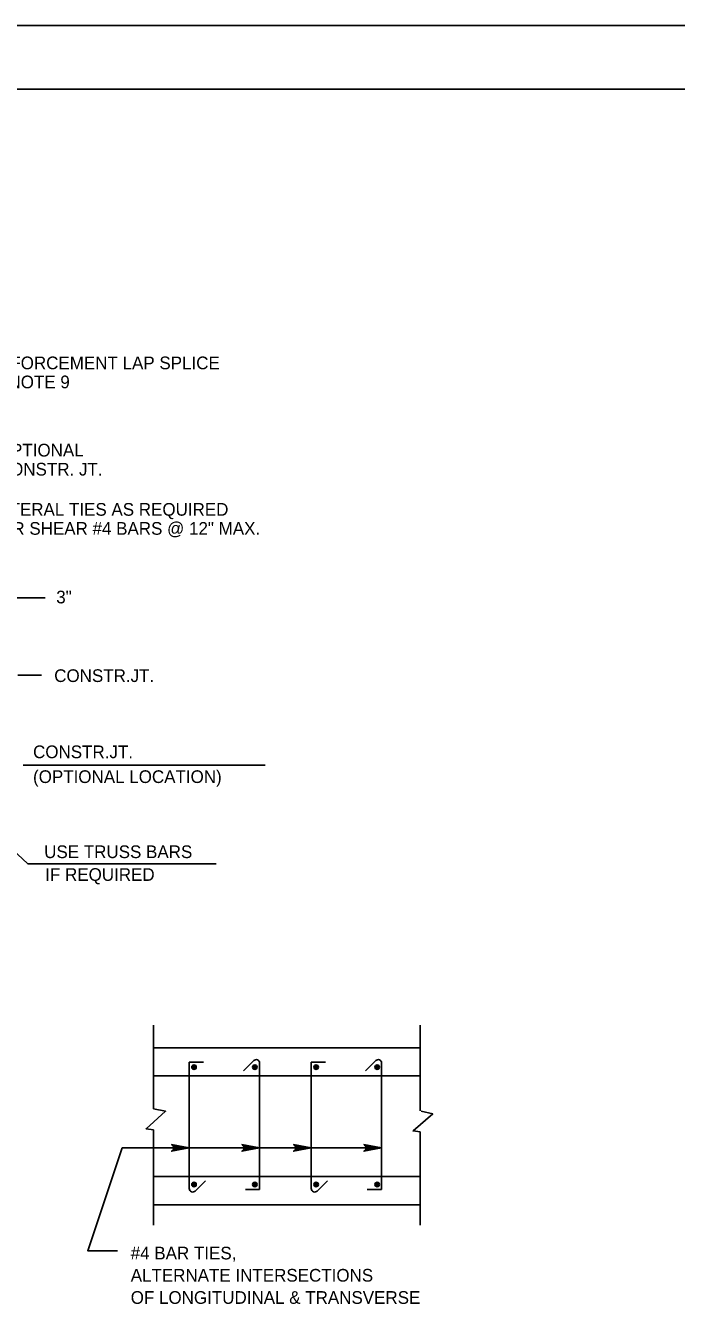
# Model space of a CAD drawing. Extents: x 639028 to 639883, y 298843 to 300031.
# Drawn here: x 639429.9 to 639583.6, y 299727.9 to 300031.1 of the extents above; entities that cross this region are included whole.
import ezdxf

# ---------------------------------------------------------------- set-up
doc = ezdxf.new("R2010")
doc.units = 0
for name, color, linetype in [('2', 7, 'Continuous'), ('52', 7, 'Continuous'), ('54', 7, 'Continuous'), ('PLT-BNDY', 7, 'Continuous')]:
    doc.layers.add(name, color=color, linetype=linetype)

msp = doc.modelspace()

# ---------------------------------------------------------------- linework, layer by layer
at = {"layer": '2'}
for p, q in [((639067.74, 300016.08), (639853.74, 300016.08)), ((639423.86, 299895.83), (639434.45, 299895.83)), ((639427.99, 299877.58), (639433.61, 299877.58)), ((639429.24, 299856.33), (639486.49, 299856.33)), ((639408.49, 299853.45), (639430.36, 299832.95)), ((639430.36, 299832.95), (639474.86, 299832.95)), ((639460.06, 299794.86), (639460.06, 299775.11)), ((639523.06, 299794.86), (639523.06, 299774.61)), ((639460.06, 299789.49), (639523.06, 299789.49)), ((639460.06, 299782.86), (639523.06, 299782.86)), ((639460.06, 299770.11), (639460.06, 299747.61)), ((639523.06, 299769.61), (639523.06, 299747.61)), ((639460.06, 299759.11), (639523.06, 299759.11)), ((639460.06, 299752.36), (639523.06, 299752.36))]:
    msp.add_line(p, q, dxfattribs=at)
for points in [[(639460.06, 299775.11), (639462.93, 299774.49), (639458.31, 299770.36), (639460.06, 299770.11)], [(639523.31, 299774.49), (639526.06, 299773.86), (639521.43, 299769.86), (639523.06, 299769.61)]]:
    msp.add_lwpolyline(points, dxfattribs=at)
at = {"layer": '52'}
msp.add_line((639452.63, 299765.83), (639513.98, 299765.83), dxfattribs=at)
for points in [[(639452.63, 299765.83), (639444.52, 299741.53), (639451.59, 299741.53)], [(639468.52, 299765.83), (639464.33, 299765.04), (639464.49, 299765.15), (639464.65, 299765.26), (639464.74, 299765.41), (639464.82, 299765.55), (639464.84, 299765.69), (639464.87, 299765.83), (639464.84, 299765.97), (639464.82, 299766.11), (639464.74, 299766.25), (639464.65, 299766.39), (639464.49, 299766.5), (639464.33, 299766.61), (639468.52, 299765.83), (639464.49, 299766.5), (639464.65, 299766.39), (639468.52, 299765.83), (639464.74, 299766.25), (639464.82, 299766.11), (639468.52, 299765.83), (639464.84, 299765.97), (639464.87, 299765.83), (639468.52, 299765.83), (639464.84, 299765.69), (639464.82, 299765.55), (639468.52, 299765.83), (639464.74, 299765.41), (639464.65, 299765.26), (639468.52, 299765.83), (639464.49, 299765.15)], [(639485.15, 299765.83), (639480.96, 299765.04), (639481.12, 299765.15), (639481.28, 299765.26), (639481.36, 299765.41), (639481.45, 299765.55), (639481.47, 299765.69), (639481.5, 299765.83), (639481.47, 299765.97), (639481.45, 299766.11), (639481.36, 299766.25), (639481.28, 299766.39), (639481.12, 299766.5), (639480.96, 299766.61), (639485.15, 299765.83), (639481.12, 299766.5), (639481.28, 299766.39), (639485.15, 299765.83), (639481.36, 299766.25), (639481.45, 299766.11), (639485.15, 299765.83), (639481.47, 299765.97), (639481.5, 299765.83), (639485.15, 299765.83), (639481.47, 299765.69), (639481.45, 299765.55), (639485.15, 299765.83), (639481.36, 299765.41), (639481.28, 299765.26), (639485.15, 299765.83), (639481.12, 299765.15)], [(639497.35, 299765.83), (639493.16, 299765.04), (639493.32, 299765.15), (639493.48, 299765.26), (639493.56, 299765.41), (639493.65, 299765.55), (639493.67, 299765.69), (639493.7, 299765.83), (639493.67, 299765.97), (639493.65, 299766.11), (639493.56, 299766.25), (639493.48, 299766.39), (639493.32, 299766.5), (639493.16, 299766.61), (639497.35, 299765.83), (639493.32, 299766.5), (639493.48, 299766.39), (639497.35, 299765.83), (639493.56, 299766.25), (639493.65, 299766.11), (639497.35, 299765.83), (639493.67, 299765.97), (639493.7, 299765.83), (639497.35, 299765.83), (639493.67, 299765.69), (639493.65, 299765.55), (639497.35, 299765.83), (639493.56, 299765.41), (639493.48, 299765.26), (639497.35, 299765.83), (639493.32, 299765.15)], [(639513.98, 299765.83), (639509.78, 299765.04), (639509.95, 299765.15), (639510.11, 299765.26), (639510.19, 299765.41), (639510.27, 299765.55), (639510.3, 299765.69), (639510.32, 299765.83), (639510.3, 299765.97), (639510.27, 299766.11), (639510.19, 299766.25), (639510.11, 299766.39), (639509.95, 299766.5), (639509.78, 299766.61), (639513.98, 299765.83), (639509.95, 299766.5), (639510.11, 299766.39), (639513.98, 299765.83), (639510.19, 299766.25), (639510.27, 299766.11), (639513.98, 299765.83), (639510.3, 299765.97), (639510.32, 299765.83), (639513.98, 299765.83), (639510.3, 299765.69), (639510.27, 299765.55), (639513.98, 299765.83), (639510.19, 299765.41), (639510.11, 299765.26), (639513.98, 299765.83), (639509.95, 299765.15)]]:
    msp.add_lwpolyline(points, dxfattribs=at)
at = {"layer": '54'}
for p, q in [((639483.75, 299786.46), (639481.33, 299784.05)), ((639512.58, 299786.46), (639510.16, 299784.05)), ((639468.52, 299756.23), (639468.52, 299786.12)), ((639468.52, 299786.12), (639471.9, 299786.12)), ((639485.15, 299785.88), (639485.15, 299755.99)), ((639497.35, 299756.23), (639497.35, 299786.12)), ((639497.35, 299786.12), (639500.73, 299786.12)), ((639513.98, 299785.88), (639513.98, 299755.99)), ((639469.93, 299755.65), (639472.34, 299758.06)), ((639485.15, 299755.99), (639481.78, 299755.99)), ((639498.75, 299755.65), (639501.17, 299758.06)), ((639513.98, 299755.99), (639510.6, 299755.99))]:
    msp.add_line(p, q, dxfattribs=at)
for centre, radius in [((639469.66, 299784.92), 0.533), ((639469.66, 299784.92), 0.4), ((639469.66, 299784.92), 0.267), ((639469.66, 299784.92), 0.133), ((639484.02, 299784.92), 0.533), ((639484.02, 299784.92), 0.4), ((639484.02, 299784.92), 0.267), ((639484.02, 299784.92), 0.133), ((639498.49, 299784.92), 0.533), ((639498.49, 299784.92), 0.4), ((639498.49, 299784.92), 0.267), ((639498.49, 299784.92), 0.133), ((639512.94, 299784.92), 0.533), ((639512.94, 299784.92), 0.4), ((639512.94, 299784.92), 0.267), ((639512.94, 299784.92), 0.133), ((639469.66, 299757.19), 0.533), ((639469.66, 299757.19), 0.4), ((639469.66, 299757.19), 0.267), ((639469.66, 299757.19), 0.133), ((639484.02, 299757.19), 0.533), ((639484.02, 299757.19), 0.4), ((639484.02, 299757.19), 0.267), ((639484.02, 299757.19), 0.133), ((639498.49, 299757.19), 0.533), ((639498.49, 299757.19), 0.4), ((639498.49, 299757.19), 0.267), ((639498.49, 299757.19), 0.133), ((639512.94, 299757.19), 0.533), ((639512.94, 299757.19), 0.4), ((639512.94, 299757.19), 0.267), ((639512.94, 299757.19), 0.133)]:
    msp.add_circle(centre, radius, dxfattribs=at)
for centre, start, end in [((639484.33, 299785.88), 0, 135), ((639513.16, 299785.88), 0, 135), ((639469.34, 299756.23), 180, 315), ((639498.17, 299756.23), 180, 315)]:
    msp.add_arc(centre, 0.821, start, end, dxfattribs=at)
at = {"layer": 'PLT-BNDY'}
msp.add_lwpolyline([(639027.74, 300031.08), (639868.74, 300031.08), (639868.74, 299437.08), (639027.74, 299437.08)], close=True, dxfattribs=at)

# ---------------------------------------------------------------- texts
at = {"layer": '2'}
for s, p in [('REINFORCEMENT LAP SPLICE', (639416.66, 299949.87)), ('SEE NOTE 9', (639416.66, 299945.37)), ('OPTIONAL', (639423.29, 299929.25)), ('CONSTR. JT.', (639423.29, 299924.75)), ('LATERAL TIES AS REQUIRED', (639421.15, 299915.25)), ('FOR SHEAR #4 BARS @ 12" MAX.', (639421.15, 299910.75)), ('3"  ', (639437.09, 299894.54)), ('CONSTR.JT.', (639436.61, 299875.95)), ('CONSTR.JT.', (639431.61, 299857.95)), ('(OPTIONAL LOCATION)', (639431.61, 299852.08)), ('USE TRUSS BARS', (639434.24, 299834.33)), ('IF REQUIRED', (639434.49, 299828.95)), ('#4 BAR TIES,', (639454.69, 299739.48)), ('ALTERNATE INTERSECTIONS', (639454.69, 299734.23)), ('OF LONGITUDINAL & TRANSVERSE', (639454.69, 299728.98))]:
    msp.add_text(s, height=3, dxfattribs=at).set_placement(p)

doc.saveas('drawing.dxf')
